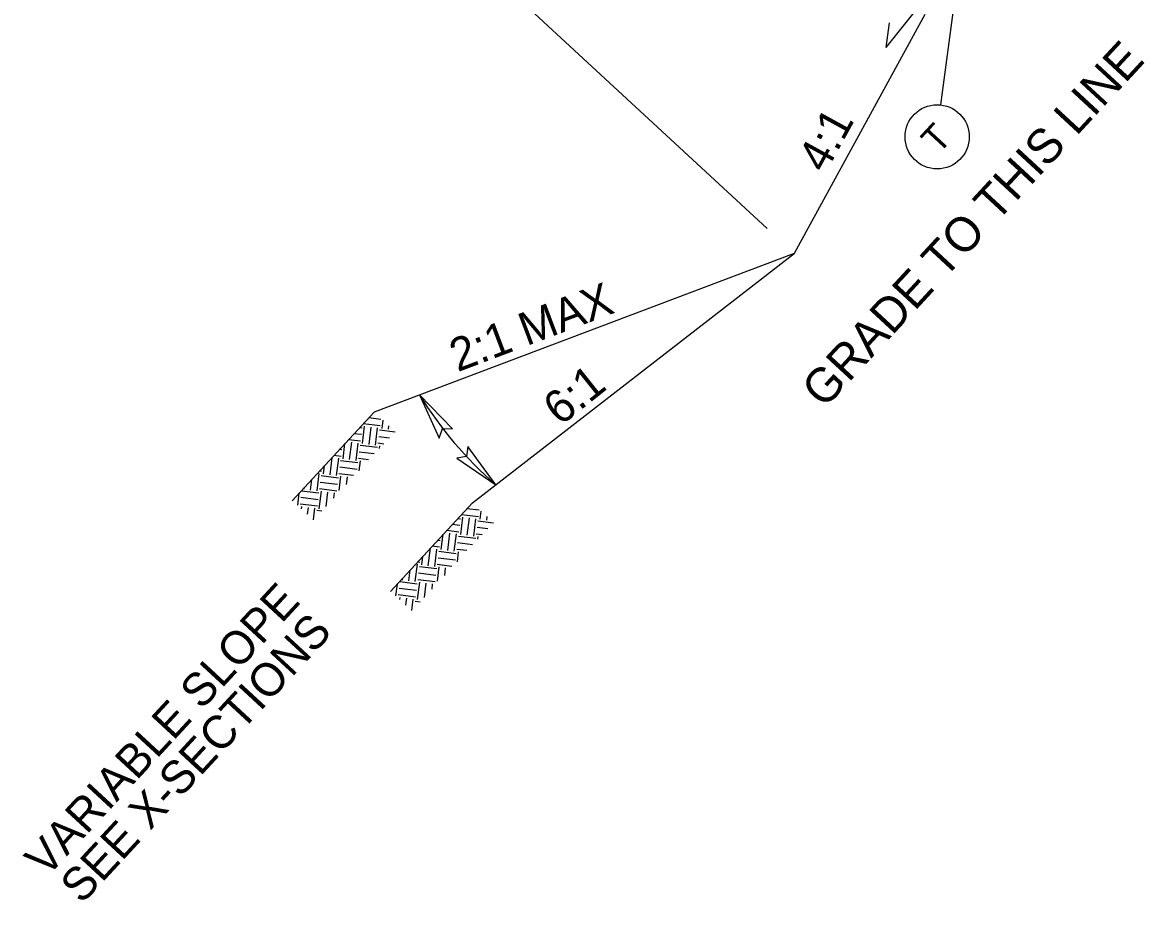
# Model space of a CAD drawing. Extents: x 1768274 to 1769121, y 999922 to 1000687.
# Drawn here: x 1768972.56 to 1769020.84, y 999934.37 to 999972.23 of the extents above; entities that cross this region are included whole.
import ezdxf

# ---------------------------------------------------------------- set-up
doc = ezdxf.new("R2010")
doc.units = 0
doc.layers.add('E_NCDOT_Terrain_Model_Triangles', color=7, linetype='Continuous')

msp = doc.modelspace()

# ---------------------------------------------------------------- linework, layer by layer
at = {"layer": 'E_NCDOT_Terrain_Model_Triangles'}
for p, q in [((1769004.6, 999963.367), (1768987.848, 999978.853)), ((1769009.719, 999971.152), (1769012.931, 999975.197)), ((1769012.705, 999973.568), (1769012.06, 999968.688)), ((1769011.389, 999972.573), (1769005.759, 999962.296)), ((1769009.719, 999971.152), (1769009.871, 999972.212)), ((1769005.759, 999962.296), (1768987.69, 999955.473)), ((1768991.919, 999951.565), (1769005.76, 999962.296)), ((1768984.166, 999951.66), (1768987.69, 999955.473)), ((1768984.166, 999951.66), (1768987.69, 999955.473)), ((1768987.98, 999955.155), (1768987.456, 999955.22)), ((1768987.98, 999955.155), (1768987.456, 999955.22)), ((1768988.028, 999954.77), (1768988.071, 999955.121)), ((1768988.028, 999954.77), (1768988.071, 999955.121)), ((1768987.177, 999954.781), (1768987.063, 999954.795)), ((1768987.177, 999954.781), (1768987.063, 999954.795)), ((1768987.189, 999954.116), (1768987.281, 999954.863)), ((1768987.189, 999954.116), (1768987.281, 999954.863)), ((1768987.946, 999954.875), (1768987.22, 999954.965)), ((1768987.946, 999954.875), (1768987.22, 999954.965)), ((1768987.469, 999954.082), (1768987.561, 999954.828)), ((1768987.469, 999954.082), (1768987.561, 999954.828)), ((1768987.749, 999954.047), (1768987.841, 999954.793)), ((1768987.749, 999954.047), (1768987.841, 999954.793)), ((1768988.591, 999954.606), (1768987.923, 999954.689)), ((1768988.591, 999954.606), (1768987.923, 999954.689)), ((1768988.307, 999954.736), (1768988.326, 999954.886)), ((1768988.307, 999954.736), (1768988.326, 999954.886)), ((1768986.351, 999953.463), (1768986.433, 999954.127)), ((1768986.351, 999953.463), (1768986.433, 999954.127)), ((1768987.107, 999954.221), (1768986.592, 999954.285)), ((1768987.107, 999954.221), (1768986.592, 999954.285)), ((1768986.631, 999953.428), (1768986.723, 999954.174)), ((1768986.631, 999953.428), (1768986.723, 999954.174)), ((1768987.142, 999954.501), (1768986.814, 999954.542)), ((1768987.142, 999954.501), (1768986.814, 999954.542)), ((1768986.91, 999953.393), (1768987.003, 999954.14)), ((1768986.91, 999953.393), (1768987.003, 999954.14)), ((1768988.102, 999954.098), (1768987.854, 999954.129)), ((1768988.102, 999954.098), (1768987.854, 999954.129)), ((1768988.347, 999954.352), (1768987.888, 999954.409)), ((1768988.347, 999954.352), (1768987.888, 999954.409)), ((1768986.304, 999953.847), (1768986.189, 999953.861)), ((1768986.304, 999953.847), (1768986.189, 999953.861)), ((1768987.695, 999953.675), (1768987.05, 999953.755)), ((1768987.695, 999953.675), (1768987.05, 999953.755)), ((1768987.831, 999953.943), (1768987.084, 999954.035)), ((1768987.831, 999953.943), (1768987.084, 999954.035)), ((1768987.921, 999953.91), (1768987.935, 999954.024)), ((1768987.921, 999953.91), (1768987.935, 999954.024)), ((1768985.512, 999952.809), (1768985.558, 999953.174)), ((1768985.512, 999952.809), (1768985.558, 999953.174)), ((1768985.792, 999952.774), (1768985.885, 999953.52)), ((1768985.792, 999952.774), (1768985.885, 999953.52)), ((1768986.269, 999953.567), (1768985.955, 999953.606)), ((1768986.269, 999953.567), (1768985.955, 999953.606)), ((1768986.072, 999952.739), (1768986.164, 999953.486)), ((1768986.072, 999952.739), (1768986.164, 999953.486)), ((1768986.992, 999953.289), (1768986.246, 999953.381)), ((1768986.992, 999953.289), (1768986.246, 999953.381)), ((1768987.451, 999953.421), (1768987.015, 999953.475)), ((1768987.451, 999953.421), (1768987.015, 999953.475)), ((1768987.044, 999952.944), (1768987.097, 999953.37)), ((1768987.044, 999952.944), (1768987.097, 999953.37)), ((1768985.234, 999952.086), (1768985.326, 999952.832)), ((1768985.234, 999952.086), (1768985.326, 999952.832)), ((1768985.431, 999952.913), (1768985.329, 999952.926)), ((1768985.431, 999952.913), (1768985.329, 999952.926)), ((1768986.154, 999952.635), (1768985.408, 999952.727)), ((1768986.154, 999952.635), (1768985.408, 999952.727)), ((1768986.799, 999952.744), (1768986.177, 999952.821)), ((1768986.799, 999952.744), (1768986.177, 999952.821)), ((1768986.183, 999952.104), (1768986.259, 999952.716)), ((1768986.183, 999952.104), (1768986.259, 999952.716)), ((1768986.958, 999953.009), (1768986.211, 999953.101)), ((1768986.958, 999953.009), (1768986.211, 999953.101)), ((1768986.498, 999952.353), (1768986.538, 999952.682)), ((1768986.498, 999952.353), (1768986.538, 999952.682)), ((1768984.674, 999952.155), (1768984.682, 999952.222)), ((1768984.674, 999952.155), (1768984.682, 999952.222)), ((1768984.954, 999952.12), (1768985.011, 999952.579)), ((1768984.954, 999952.12), (1768985.011, 999952.579)), ((1768986.085, 999952.075), (1768985.339, 999952.167)), ((1768986.085, 999952.075), (1768985.339, 999952.167)), ((1768986.119, 999952.355), (1768985.373, 999952.447)), ((1768986.119, 999952.355), (1768985.373, 999952.447)), ((1768984.4, 999951.471), (1768984.464, 999951.984)), ((1768984.4, 999951.471), (1768984.464, 999951.984)), ((1768985.281, 999951.701), (1768984.535, 999951.793)), ((1768985.281, 999951.701), (1768984.535, 999951.793)), ((1768985.315, 999951.981), (1768984.569, 999952.073)), ((1768985.315, 999951.981), (1768984.569, 999952.073)), ((1768985.328, 999951.316), (1768985.42, 999952.063)), ((1768985.328, 999951.316), (1768985.42, 999952.063)), ((1768985.623, 999951.407), (1768985.7, 999952.028)), ((1768985.623, 999951.407), (1768985.7, 999952.028)), ((1768985.951, 999951.762), (1768985.98, 999951.993)), ((1768985.951, 999951.762), (1768985.98, 999951.993)), ((1768985.246, 999951.421), (1768984.5, 999951.513)), ((1768985.246, 999951.421), (1768984.5, 999951.513)), ((1768984.57, 999951.314), (1768984.582, 999951.409)), ((1768984.57, 999951.314), (1768984.582, 999951.409)), ((1768984.825, 999951.078), (1768984.862, 999951.374)), ((1768984.825, 999951.078), (1768984.862, 999951.374)), ((1768985.08, 999950.842), (1768985.141, 999951.339)), ((1768985.08, 999950.842), (1768985.141, 999951.339)), ((1768985.439, 999951.208), (1768985.223, 999951.235)), ((1768985.439, 999951.208), (1768985.223, 999951.235)), ((1768988.394, 999947.752), (1768991.919, 999951.565)), ((1768988.394, 999947.752), (1768991.919, 999951.565)), ((1768992.209, 999951.246), (1768991.685, 999951.311)), ((1768992.209, 999951.246), (1768991.685, 999951.311)), ((1768992.256, 999950.862), (1768992.3, 999951.213)), ((1768992.256, 999950.862), (1768992.3, 999951.213)), ((1768991.405, 999950.872), (1768991.292, 999950.886)), ((1768991.405, 999950.872), (1768991.292, 999950.886)), ((1768991.418, 999950.208), (1768991.51, 999950.954)), ((1768991.418, 999950.208), (1768991.51, 999950.954)), ((1768992.174, 999950.966), (1768991.449, 999951.056)), ((1768992.174, 999950.966), (1768991.449, 999951.056)), ((1768991.698, 999950.173), (1768991.79, 999950.919)), ((1768991.698, 999950.173), (1768991.79, 999950.919)), ((1768991.977, 999950.139), (1768992.07, 999950.885)), ((1768991.977, 999950.139), (1768992.07, 999950.885)), ((1768992.82, 999950.697), (1768992.151, 999950.78)), ((1768992.82, 999950.697), (1768992.151, 999950.78)), ((1768992.536, 999950.827), (1768992.555, 999950.977)), ((1768992.536, 999950.827), (1768992.555, 999950.977)), ((1768991.336, 999950.313), (1768990.82, 999950.376)), ((1768991.336, 999950.313), (1768990.82, 999950.376)), ((1768990.859, 999949.519), (1768990.952, 999950.265)), ((1768990.859, 999949.519), (1768990.952, 999950.265)), ((1768991.371, 999950.592), (1768991.043, 999950.633)), ((1768991.371, 999950.592), (1768991.043, 999950.633)), ((1768992.575, 999950.443), (1768992.117, 999950.5)), ((1768992.575, 999950.443), (1768992.117, 999950.5)), ((1768990.532, 999949.938), (1768990.418, 999949.953)), ((1768990.532, 999949.938), (1768990.418, 999949.953)), ((1768990.579, 999949.554), (1768990.662, 999950.218)), ((1768990.579, 999949.554), (1768990.662, 999950.218)), ((1768991.139, 999949.485), (1768991.231, 999950.231)), ((1768991.139, 999949.485), (1768991.231, 999950.231)), ((1768991.924, 999949.766), (1768991.278, 999949.846)), ((1768991.924, 999949.766), (1768991.278, 999949.846)), ((1768992.059, 999950.034), (1768991.313, 999950.126)), ((1768992.059, 999950.034), (1768991.313, 999950.126)), ((1768992.331, 999950.19), (1768992.082, 999950.22)), ((1768992.331, 999950.19), (1768992.082, 999950.22)), ((1768992.15, 999950.001), (1768992.164, 999950.116)), ((1768992.15, 999950.001), (1768992.164, 999950.116)), ((1768990.021, 999948.865), (1768990.113, 999949.611)), ((1768990.021, 999948.865), (1768990.113, 999949.611)), ((1768990.498, 999949.659), (1768990.183, 999949.698)), ((1768990.498, 999949.659), (1768990.183, 999949.698)), ((1768990.301, 999948.831), (1768990.393, 999949.577)), ((1768990.301, 999948.831), (1768990.393, 999949.577)), ((1768991.221, 999949.38), (1768990.475, 999949.472)), ((1768991.221, 999949.38), (1768990.475, 999949.472)), ((1768991.679, 999949.513), (1768991.244, 999949.566)), ((1768991.679, 999949.513), (1768991.244, 999949.566)), ((1768991.273, 999949.036), (1768991.326, 999949.462)), ((1768991.273, 999949.036), (1768991.326, 999949.462)), ((1768989.462, 999948.177), (1768989.555, 999948.923)), ((1768989.462, 999948.177), (1768989.555, 999948.923)), ((1768989.659, 999949.005), (1768989.558, 999949.017)), ((1768989.659, 999949.005), (1768989.558, 999949.017)), ((1768990.382, 999948.726), (1768989.636, 999948.818)), ((1768990.382, 999948.726), (1768989.636, 999948.818)), ((1768989.741, 999948.9), (1768989.786, 999949.266)), ((1768989.741, 999948.9), (1768989.786, 999949.266)), ((1768991.028, 999948.836), (1768990.406, 999948.912)), ((1768991.028, 999948.836), (1768990.406, 999948.912)), ((1768990.412, 999948.195), (1768990.487, 999948.808)), ((1768990.412, 999948.195), (1768990.487, 999948.808)), ((1768991.186, 999949.1), (1768990.44, 999949.192)), ((1768991.186, 999949.1), (1768990.44, 999949.192)), ((1768988.903, 999948.246), (1768988.911, 999948.313)), ((1768988.903, 999948.246), (1768988.911, 999948.313)), ((1768989.183, 999948.211), (1768989.239, 999948.67)), ((1768989.183, 999948.211), (1768989.239, 999948.67)), ((1768990.348, 999948.446), (1768989.602, 999948.538)), ((1768990.348, 999948.446), (1768989.602, 999948.538)), ((1768990.726, 999948.444), (1768990.767, 999948.773)), ((1768990.726, 999948.444), (1768990.767, 999948.773)), ((1768988.629, 999947.562), (1768988.692, 999948.075)), ((1768988.629, 999947.562), (1768988.692, 999948.075)), ((1768989.509, 999947.792), (1768988.763, 999947.884)), ((1768989.509, 999947.792), (1768988.763, 999947.884)), ((1768989.544, 999948.072), (1768988.798, 999948.164)), ((1768989.544, 999948.072), (1768988.798, 999948.164)), ((1768989.557, 999947.408), (1768989.649, 999948.154)), ((1768989.557, 999947.408), (1768989.649, 999948.154)), ((1768990.313, 999948.166), (1768989.567, 999948.259)), ((1768990.313, 999948.166), (1768989.567, 999948.259)), ((1768989.852, 999947.498), (1768989.929, 999948.119)), ((1768989.852, 999947.498), (1768989.929, 999948.119)), ((1768990.18, 999947.853), (1768990.208, 999948.085)), ((1768990.18, 999947.853), (1768990.208, 999948.085)), ((1768989.475, 999947.512), (1768988.729, 999947.605)), ((1768989.475, 999947.512), (1768988.729, 999947.605)), ((1768988.799, 999947.405), (1768988.811, 999947.5)), ((1768988.799, 999947.405), (1768988.811, 999947.5)), ((1768989.054, 999947.169), (1768989.09, 999947.465)), ((1768989.054, 999947.169), (1768989.09, 999947.465)), ((1768989.309, 999946.934), (1768989.37, 999947.431)), ((1768989.309, 999946.934), (1768989.37, 999947.431)), ((1768989.668, 999947.299), (1768989.452, 999947.326)), ((1768989.668, 999947.299), (1768989.452, 999947.326))]:
    msp.add_line(p, q, dxfattribs=at)
for points in [[(1768991.055, 999954.756), (1768989.643, 999956.211), (1768990.484, 999954.352), (1768990.633, 999954.763)], [(1768991.245, 999953.484), (1768992.919, 999952.34), (1768991.724, 999953.994), (1768991.66, 999953.561)]]:
    msp.add_lwpolyline(points, close=True, dxfattribs=at)
msp.add_circle((1769011.916, 999967.315), 1.381, dxfattribs=at)
msp.add_arc((1769004.259, 999965.256), 17.188, 211.7524, 228.7178, dxfattribs=at)

# ---------------------------------------------------------------- texts
for s, height, rotation, p in [('GRADE TO THIS LINE', 1.48344, 47.2512, (1769007.056, 999955.583)), ('4:1', 1.421, 61.2873, (1769007.101, 999965.702)), ('T', 1.137, 47.2509, (1769011.969, 999966.531)), ('2:1 MAX', 1.421, 20.686, (1768991.282, 999957.185)), ('6:1', 1.421, 38.645, (1768995.702, 999954.847)), ('VARIABLE SLOPE', 1.42097, 47.2512, (1768973.595, 999935.41)), ('SEE X-SECTIONS', 1.42097, 47.2512, (1768975.111, 999934.266))]:
    msp.add_text(s, height=height, rotation=rotation, dxfattribs=at).set_placement(p)

doc.saveas('drawing.dxf')
